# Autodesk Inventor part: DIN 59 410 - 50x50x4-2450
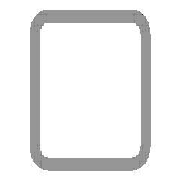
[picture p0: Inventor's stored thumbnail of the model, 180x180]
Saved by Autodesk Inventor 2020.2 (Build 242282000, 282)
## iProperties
Manager: www.cadconsulting.pl
Company: Fabian Stasiak CAD Consulting
Created: 2015-01
Part Number: DIN 59 410 - 50x50x4-2450
Material: Stal, miękka
Description: Rurki stalowe o przekroju kwadratowym formowane na gorąco
Document SubType Name: Modellieren
Standard: DIN
Designer: F.Stasiak
Standards Organization: DIN
Language: pl-PL
Size Designation: 50x50x4
Categories: <MemberInstance><Categories><Category DisplayName="Kształtowniki konstrukcyjne" InternalName="089c4875-fa83-4c05-b084-43b9cc11f5ed" Mnemonic="GRDR"><CategoryPar
Stock Number: 50x50x4
Density: 7.85 g/cm^3
Appearance: Częściowo polerowana
Mass: 13362.7 g
Surface Area: 8525.15 cm^2
Volume: 1702.25 cm^3
Catalog Web Link: www.expertbooks.pl
_CCFamilyMember: 40
_CCFamilyDisplayName: DIN 59410 (Kwadrat) - Rurki stalowe o przekroju kwadratowym formowane na gorąco
_FrameMemberDoc: Frame Member File
_Version: 15.0.0
_GetPNFromCC: 1
G_W: 50,000 mm
G_H: 50,000 mm
+714BB85C-1DBA-47A2-8727-1192C7FCAE58+CUTDETAIL1: Wytnij
+D68C6693-2217-4D6A-B527-1A8CC3359307+CUTDETAIL2: Wytnij
G_L: 2450,000 mm
IsCustomPart: 1
Author: F.Stasiak
Subject: Zbiór ćwiczeń. Autodesk Inventor 2020. Kurs Professional
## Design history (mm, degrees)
node "Płaszczyzna początkowa"
node "Płaszczyzna końcowa"
sketch "Szkic"
  geometry: L1 (-17, 25)-(17, 25); L2 (25, 17)-(25, -17); L3 (17, -25)-(-17, -25); L4 (-25, -17)-(-25, 17); L5 (-37.32, 0)-(37.32, 0) reference; L6 (0, -37.32)-(0, 37.32) reference; L7 (-17, 21)-(17, 21); L8 (21, 17)-(21, -17); L9 (17, -21)-(-17, -21); L10 (-21, -17)-(-21, 17); A1 r 8 centre (-17, 17) between (-17, 25) and (-25, 17); A2 r 8 centre (17, 17) between (25, 17) and (17, 25); A3 r 8 centre (17, -17) between (17, -25) and (25, -17); A4 r 8 centre (-17, -17) between (-25, -17) and (-17, -25); A5 r 4 centre (-17, 17) between (-17, 21) and (-21, 17); A6 r 4 centre (17, 17) between (21, 17) and (17, 21); A7 r 4 centre (17, -17) between (17, -21) and (21, -17); A8 r 4 centre (-17, -17) between (-21, -17) and (-17, -21); 3 further points
  constraints: 16 end point, 16 point on circle, 8 centre point, 8 tangent, 6 point on line, 4 parallel, 3 equal radius, 3 perpendicular, 1 horizontal, 7 other
  dimensions: "b" = 50 distance of point (-25, 25) point (25, 25); "msp_r" = 8 radius of A1 (= 2 x ParT); "d8" = 25 distance between parallel lines of L4 L6 (= d9); "d9" = 25 distance between parallel lines of L3 L5 (= 0.5 x b); "d10" = 4 distance between parallel lines of L3 L9 (= ParT)
extrude "Bryła" new body sketch "Szkic" taper "d4" = 0 deg; stored distance "NLG" = 10
node "Driven Length"
  sketch "Sketch2"
    geometry: L1 (0, 0)-(10, 0) reference
    constraints: 2 end point, 1 horizontal
  workplane "Work Plane3"
  sketch "Sketch3"
    geometry: L1 (-2, 25)-(12, 25) reference; L2 (-2, 2475)-(12, 2475) reference
    dimensions: "d14" = 2450 distance between parallel lines of L1 L2 (derived)
node "Płaszczyzna konstrukcyjna4"
feature "Podział1"
node "Płaszczyzna konstrukcyjna5"
feature "Podział2"
body "Solid1"
other parameters: "ParT" = 4, "G_OFFSET_START" = -25 [user parameter; used in 1 equation term], "G_OFFSET_END" = -25 [user parameter; used in 1 equation term], "d11" = 25 (= -G_OFFSET_START), "d12" = 2475 (= G_OFFSET_END + B_L), "G_L" = 2450 (= d14) [user parameter], "d13" = 90 deg
